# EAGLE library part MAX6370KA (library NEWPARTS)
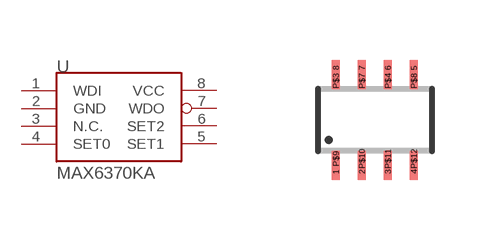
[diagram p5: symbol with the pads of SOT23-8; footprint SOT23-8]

Designator prefix -

## MAX6370KA  [SOT23-8]
1  WDI
2  GND
3  N.C.  nc
4  SET0
5  SET1
6  SET2
7  WDO
8  VCC

## Footprint SOT23-8 (pad centres in mm)
Small Outline Transistor 8 lead
smd 0.203 x 0.406: 1 -0.975,-1.3; 2 -0.325,-1.3; 3 0.325,-1.3; 4 0.975,-1.3; 5 0.975,1.3; 6 0.325,1.3; 7 -0.325,1.3; 8 -0.975,1.3; P$3 -0.975,0.975; P$4 0.325,0.975; P$7 -0.325,0.975; P$8 0.975,0.975; P$9 -0.975,-0.975; P$10 -0.325,-0.975; P$11 0.325,-0.975; P$12 0.975,-0.975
